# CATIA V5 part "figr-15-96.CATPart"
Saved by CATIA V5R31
Part number: Part1
Bounding box of the stored display mesh (mm): x -31.325 to 48, y -66.072 to 47.73, z 0 to 2
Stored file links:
  D:\PROJECTS\Project 2021\US EDITION\CATIA V5 6R 2021\Resources\Part Files\c15_catia_v5_6r2021_prt\figr-15-96.CATPart
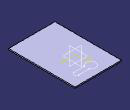
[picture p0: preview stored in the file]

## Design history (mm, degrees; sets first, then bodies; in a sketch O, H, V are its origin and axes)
SheetMetalParameters1: Thickness 2, BendRadius 4, KFactor 0.400515 {= log(min(100,max(20*SheetMetalParameters1.BendRadius,SheetMetalParameters1.Thickness)/SheetMetalParameters1.Thickness))/log(100)/2}, ReliefRadialLength 1, ReliefAxialLength 2, MinimumBendRadius 0
Body1 (main body)
  Sketch1 on xy-plane, origin (0, 0, 0), H (1, 0, 0), V (0, 1, 0)
    line L1 (-31.3255, 47.7299) -> (48, 47.7299)
    line L2 (48, 47.7299) -> (48, -66.0715)
    line L3 (48, -66.0715) -> (-31.3255, -66.0715)
    line L4 (-31.3255, -66.0715) -> (-31.3255, 47.7299)
    horizontal: L1 H, L3 H
    vertical: L2 V, L4 V
  Wall1: Thickness 2, Profile Sketch1, OffsetValue 0
  Sketch2 on face of Wall1, origin (0, 0, 2), H (1, 0, 0), V (0, 1, 0)
    construction line L1 (2.2258, 29) -> (27.2258, 29)
    point P1 (2.2258, 29)
    point P2 (27.2258, 29)
    line L2 (27.2258, 25) -> (9.154, 25)
    line L3 (9.154, 33) -> (27.2258, 33)
    arc A1 centre (2.2258, 29) radius 8 from (9.154, 25) to (9.154, 33) cw
    arc A2 centre (27.2258, 29) radius 4 from (27.2258, 33) to (27.2258, 25) cw
    radius A1 = 8
    radius A2 = 4
    distance P2 P1 = 25
    horizontal: L1 H
    tangency: A2 L2, A2 L3
    parallelism: L2 L3, L2 L1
